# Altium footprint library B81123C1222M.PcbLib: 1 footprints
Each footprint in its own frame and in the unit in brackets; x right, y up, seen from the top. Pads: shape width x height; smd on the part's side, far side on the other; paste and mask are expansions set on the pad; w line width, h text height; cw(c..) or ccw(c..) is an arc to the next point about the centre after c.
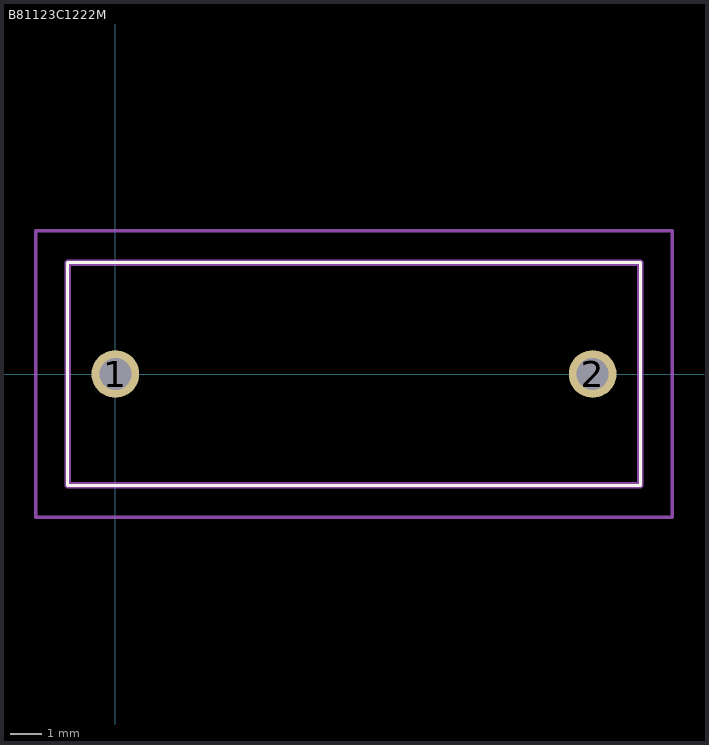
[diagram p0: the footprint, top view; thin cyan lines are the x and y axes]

## B81123C1222M [mm]
pads (2):
  round 1.5 hole 1: 1(0,0) 2(15,0)
Top Overlay:
  lines w0.1: -1.5,-3.5 16.5,-3.5 16.5,3.5 -1.5,3.5 -1.5,-3.5
Mechanical 15:
  lines w0.2: -1.5,-3.5 16.5,-3.5 16.5,3.5 -1.5,3.5 -1.5,-3.5
Mechanical 20:
  lines w0.1: -2.5,-4.5 17.5,-4.5 17.5,4.5 -2.5,4.5 -2.5,-4.5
